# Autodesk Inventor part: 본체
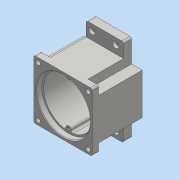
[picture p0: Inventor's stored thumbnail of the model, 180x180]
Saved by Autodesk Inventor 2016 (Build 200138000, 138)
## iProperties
Created: 2020-08
Part Number: 본체
Material: 일반
Document SubType Name: Modeling
Designer: User
Density: 1 g/cm^3
Appearance: 기본값
Mass: 324.617 g
Surface Area: 793.597 cm^2
Volume: 324.617 cm^3
Author: User
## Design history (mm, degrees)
sketch "스케치1"
  geometry: L1 (-47, 47)-(47, 47); L2 (47, 47)-(47, -47); L3 (47, -47)-(-47, -47); L4 (-47, -47)-(-47, 47); L5 (-47, 47)-(47, -47); L6 (47, 47)-(-47, -47); 1 further point
  constraints: 12 end point, 2 midpoint, 2 parallel, 1 horizontal, 1 perpendicular
  dimensions: "d0" = 94 distance of L2.end L3.end; "d1" = 94 distance of L1.end L2.end
extrude "돌출1" new body sketch "스케치1" distance "d2" = 80; taper "d3" = 0 deg
sketch "스케치2"
  geometry: L1 (30, -70)-(-30, -70); L2 (-30, -70)-(-30, 70); L3 (-30, 70)-(30, 70); L4 (30, 70)-(30, -70); L5 (30, -70)-(-30, 70); L6 (-30, -70)-(30, 70); 1 further point
  constraints: 12 end point, 2 midpoint, 2 parallel, 1 horizontal, 1 perpendicular
  dimensions: "d4" = 60 distance between parallel lines of L4 L2; "d5" = 140 distance between parallel lines of L3 L1
extrude "돌출2" join sketch "스케치2" distance "d6" = 13; taper "d7" = 0 deg
sketch "스케치3"
  geometry: L1 (30, -47)-(47, -47) reference; L2 (47, -47)-(47, 47) reference; L3 (47, 47)-(30, 47) reference; L4 (30, 70)-(30, 47) reference; L5 (-30, 70)-(30, 70) reference; L6 (-30, 47)-(-30, 70) reference; L7 (-30, 47)-(-47, 47) reference; L8 (-47, 47)-(-47, -47) reference; L9 (-47, -47)-(-30, -47) reference; L10 (-30, -70)-(-30, -47) reference; L11 (30, -70)-(-30, -70) reference; L12 (30, -47)-(30, -70) reference; L13 (-47, -47)-(-30, -47); L14 (-30, -47)-(-30, -33); L15 (-30, -33)-(-47, -33); L16 (-47, -33)-(-47, -47); L17 (-30, -70)-(-30, -47) reference; L18 (-47, 47)-(-30, 47); L19 (-30, 47)-(-30, 33); L20 (-30, 33)-(-47, 33); L21 (-47, 33)-(-47, 47); L22 (47, -47)-(30, -47); L23 (30, -47)-(30, -33); L24 (30, -33)-(47, -33); L25 (47, -33)-(47, -47); L26 (47, 47)-(30, 47) reference; L27 (47, 47)-(30, 47); L28 (30, 47)-(30, 33); L29 (30, 33)-(47, 33); L30 (47, 33)-(47, 47); L31 (-30, 47)-(-30, 70) reference; L32 (30, 70)-(30, 47) reference; L33 (30, -47)-(30, -70) reference; 1 further point
  constraints: 32 end point, 8 parallel, 4 collinear, 4 horizontal, 4 perpendicular, 1 point on line
  dimensions: "d8" = 14 distance between parallel lines of L9 L15; "d9" = 14 distance of L18.end L19.end; "d10" = 14 distance of L22.end L23.end; "d11" = 14 distance of L28.end L27.end
extrude "돌출3" cut sketch "스케치3" distance "d12" = 70; taper "d13" = 0 deg
sketch "스케치4"
  geometry: C1 r 27.5 at (-11, 0); 1 further point
  constraints: 1 centre point, 1 horizontal alignment
  dimensions: "d14" = 55 diameter of C1; "d15" = 11 distance of point (0, 0) C1.centre
extrude "돌출4" join sketch "스케치4" distance "d16" = 7; taper "d17" = 0 deg
sketch "스케치5"
  geometry: C1 r 27.5 at (0, 0) reference; 1 further point
hole "구멍1" sketch "스케치5" at (0, 0) diameter "d18" = 25; stored, may be unused: countersink angle "d22" = 90 deg, drill point angle "d24" = 0 deg; dims "d19" = 6, "d20" = 32, "d21" = 8.3, "d23" = 20
sketch "스케치6"
  geometry: L1 (-30, -33)-(-47, -33) reference; L2 (47, 47)-(-47, 47) reference; L3 (-47, 47)-(-47, -47) reference; L4 (-47, -47)-(47, -47) reference; L5 (47, -47)-(47, 47) reference; C1 r 27.5 at (-11, 0) reference; C2 r 43 at (0, 0); 1 further point
  constraints: 1 centre point, 1 coincident
  dimensions: "d25" = 86 diameter of C2
extrude "돌출5" cut sketch "스케치6" distance "d26" = 9; taper "d27" = 0 deg
sketch "스케치7"
  geometry: C1 r 43 at (0, 0) reference; C2 r 40 at (0, 0); 1 further point
  constraints: 1 centre point, 1 coincident
  dimensions: "d28" = 80 diameter of C2
extrude "돌출6" cut sketch "스케치7" distance "d29" = 62; taper "d30" = 0 deg
sketch "스케치8"
  geometry: C1 r 12.5 at (-11, 0) reference; A1 r 21 centre (-11, 0) between (6.119, 12.163) and (6.119, -12.163); A2 r 15 centre (20, 0) between (10.47, -11.584) and (10.47, 11.584); A3 r 3 centre (8.565, 13.901) between (6.119, 12.163) and (10.47, 11.584); A4 r 3 centre (8.565, -13.901) between (10.47, -11.584) and (6.119, -12.163); 1 further point
  constraints: 8 point on circle, 4 centre point, 4 tangent, 1 coincident, 1 horizontal alignment
  dimensions: "d31" = 42 diameter of A1; "d32" = 30 diameter of A2; "d33" = 20 distance of A2.centre point (0, 0); "d34" = 6 diameter of A3; "d35" = 6 diameter of A4
extrude "돌출7" join sketch "스케치8" distance "d36" = 7; taper "d37" = 0 deg
sketch "스케치9"
  geometry: C1 r 9.5 at (20, 0); A1 r 15 centre (20, 0) between (10.47, -11.584) and (10.47, 11.584) reference; 1 further point
  constraints: 1 centre point, 1 coincident
  dimensions: "d38" = 19 diameter of C1
extrude "돌출8" cut sketch "스케치9" distance "d39" = 10; taper "d40" = 0 deg
sketch "스케치10"
  geometry: C1 r 17.5 at (-11, 0); A1 r 21 centre (-11, 0) between (6.119, 12.163) and (6.119, -12.163) reference; 1 further point
  constraints: 1 centre point, 1 coincident
  dimensions: "d41" = 35 diameter of C1
extrude "돌출9" cut sketch "스케치10" distance "d42" = 10; taper "d43" = 0 deg
sketch "스케치11"
  geometry: C1 r 40 at (0, 0) reference; C2 r 43 at (0, 0) reference; A1 r 36 centre (0, 0) between (0, 36) and (-4.045, 35.772); A2 r 4 centre (0, 36) between (-3.995, 36.19) and (3.995, 36.19); A3 r 3 centre (6.992, 36.333) between (7.559, 39.279) and (4.045, 35.772); A4 r 3 centre (-6.992, 36.333) between (-4.045, 35.772) and (-7.559, 39.279); A5 r 40 centre (0, 0) between (-7.559, 39.279) and (7.559, 39.279) reference; 1 further point
  constraints: 13 point on circle, 4 centre point, 4 tangent, 1 coincident, 1 vertical alignment
  dimensions: "d44" = 72 diameter of A1; "d45" = 8 diameter of A2; "d46" = 6 diameter of A3; "d47" = 6 diameter of A4
extrude "돌출10" join sketch "스케치11" distance "d48" = 71; taper "d49" = 0 deg
sketch "스케치12"
  geometry: A1 r 4 centre (0, 36) between (-3.995, 36.19) and (3.995, 36.19) reference; 1 further point
hole "구멍2" sketch "스케치12" at (0, 36) diameter "d50" = 3.242; stored, may be unused: countersink angle "d54" = 90 deg, drill point angle "d56" = 118 deg; dims "d51" = 7, "d52" = 32, "d53" = 8.3, "d55" = 9
sketch "스케치13"
  geometry: L1 (47, -47)-(47, 47) reference; L2 (-47, -47)-(47, -47) reference; C1 r 3.5 at (40, -40); 1 further point
  constraints: 1 centre point
  dimensions: "d57" = 7 diameter of C1; "d58" = 7 distance from line of L1 C1.centre; "d59" = 7 distance from line of L2 C1.centre
extrude "돌출11" cut sketch "스케치13" distance "d60" = 71; taper "d61" = 0 deg
sketch "스케치14"
  geometry: 2 further points
  dimensions: "d68" = 17 horizontal distance of point (0, 0) point (17, 60); "d69" = 60 vertical distance of point (0, 0) point (17, 60)
hole "구멍3" sketch "스케치14" at (17, 60) diameter "d70" = 4.5; stored, may be unused: countersink angle "d74" = 90 deg, drill point angle "d76" = 118 deg; dims "d71" = 7, "d72" = 10, "d73" = 5, "d75" = 9
sketch "스케치15" dims "d0" = 94, "d1" = 94
  geometry: L1 (94, 0)-(0, 0) reference; 3 further points
  constraints: 1 midpoint, 1 vertical alignment, 1 other
  dimensions: "d83" = 40 distance from line of point (47, 40) L1
feature "엠보싱1" sketch "스케치15" dims "d0" = 94, "d1" = 94, "d84" = 0.5, "d85" = 0
chamfer "모따기1" distance "d86" = 0.8; stored, may be unused: second distance "d87" = 2, angle "d88" = 30 deg
fillet "모깎기1" dims "d89" = 3
fillet "모깎기2" dims "d90" = 3
sketch "스케치17"
  geometry: C1 r 17.5 at (-11, 0) reference; C2 r 9.5 at (20, 0) reference; C3 r 11 at (20, 0); A1 r 15 centre (20, 0) between (10.47, -11.584) and (10.47, 11.584) reference; A2 r 3 centre (8.565, 13.901) between (6.119, 12.163) and (10.47, 11.584) reference; A3 r 21 centre (-11, 0) between (6.119, 12.163) and (6.119, -12.163) reference; A4 r 3 centre (8.565, -13.901) between (10.47, -11.584) and (6.119, -12.163) reference; 1 further point
  constraints: 1 centre point, 1 coincident
  dimensions: "d95" = 22 diameter of C3
extrude "돌출12" cut sketch "스케치17" distance "d96" = 7; taper "d97" = 0 deg
chamfer "모따기3" distance "d98" = 1; stored, may be unused: second distance "d99" = 2, angle "d100" = 30 deg
fillet "모깎기4" dims "d101" = 3
node "솔리드1"
pattern_linear "직사각형 패턴1" dims "d64" = 80
pattern_linear "직사각형 패턴2" dims "d79" = 38
mirror "대칭2"
node "투영된 루프1"
node "투영된 루프2"
node "투영된 루프3"
node "투영된 루프4"
node "투영된 루프5"
node "투영된 루프7"
